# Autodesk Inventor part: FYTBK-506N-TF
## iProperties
Company: Engineering Services Northland (1988) Ltd
Author: Malcolm
Shininess: 60.0
PropertySet Name: _Private Model Information
Created: 2001-06
Part Number: FYTBK-506N-TF
Material: Stainless Steel, Austenitic
Description: 2 Hole Flange P/F Bearing, 30mm FYTBK-506N-TF
Document SubType Name: Modeling
Designer: Malcolm
Control State: 0
Master: False
Checked Out: False
PropertySet Name: Design Tracking Control
Density: 0.0
Volumn: 0.0
Area: 0.0
PropertySet Name: Model Information
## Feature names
1. Revolution1
2. Hole1
3. Hole2
4. Fillet1
5. Extrusion1
6. Extrusion2
7. Extrusion3
8. Extrusion7
9. Extrusion5
10. Fillet3
11. Fillet4
12. Fillet5
13. Extrusion6
14. Fillet7
